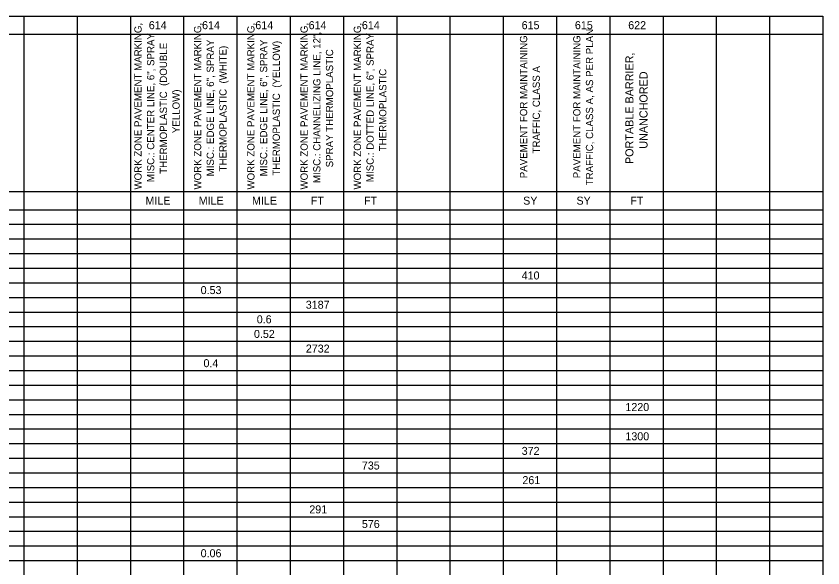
# Model space of a CAD drawing. Extents: x 91011267 to 91022583, y 37007614 to 37014266.
# Drawn here: x 91012044 to 91012802, y 37010707 to 37011225 of the extents above; entities that cross this region are included whole.
import ezdxf

# ---------------------------------------------------------------- set-up
doc = ezdxf.new("R2010")
doc.units = 0
doc.layers.add('SC_Scratch2', color=7, linetype='Continuous')
doc.layers.add('SH_Data', color=7, linetype='Continuous')

msp = doc.modelspace()

# ---------------------------------------------------------------- linework, layer by layer
at = {"layer": 'SC_Scratch2'}
msp.add_lwpolyline([(91011277.35, 37011225.45), (91012802.35, 37011225.45), (91012802.35, 37010175.45), (91011277.35, 37010175.45)], close=True, dxfattribs=at)
at = {"layer": 'SH_Data'}
for p, q in [((91012000.97, 37011225.45), (91012551.92, 37011225.45)), ((91012051.05, 37011225.45), (91012051.05, 37011134.52)), ((91012101.14, 37011225.45), (91012101.14, 37011134.52)), ((91012151.23, 37011225.45), (91012151.23, 37011134.52)), ((91012201.31, 37011225.45), (91012201.31, 37011134.52)), ((91012251.4, 37011225.45), (91012251.4, 37011134.52)), ((91012301.49, 37011225.45), (91012301.49, 37011134.52)), ((91012351.57, 37011225.45), (91012351.57, 37011134.52)), ((91012401.66, 37011225.45), (91012401.66, 37011134.52)), ((91012451.75, 37011225.45), (91012451.75, 37011134.52)), ((91012501.83, 37011225.45), (91012501.83, 37011134.52)), ((91012551.92, 37011225.45), (91012602, 37011225.45)), ((91012551.92, 37011225.45), (91012551.92, 37011134.52)), ((91012602, 37011225.45), (91012652.09, 37011225.45)), ((91012602, 37011225.45), (91012602, 37011134.52)), ((91012652.09, 37011225.45), (91012702.18, 37011225.45)), ((91012652.09, 37011225.45), (91012652.09, 37011134.52)), ((91012702.18, 37011225.45), (91012802.35, 37011225.45)), ((91012702.18, 37011225.45), (91012702.18, 37011134.52)), ((91012752.26, 37011225.45), (91012752.26, 37011134.52)), ((91012802.35, 37011225.45), (91012802.35, 37011134.52)), ((91012000.97, 37011208.44), (91012551.92, 37011208.44)), ((91012551.92, 37011208.44), (91012602, 37011208.44)), ((91012602, 37011208.44), (91012652.09, 37011208.44)), ((91012652.09, 37011208.44), (91012702.18, 37011208.44)), ((91012702.18, 37011208.44), (91012802.35, 37011208.44)), ((91012051.05, 37011134.52), (91012051.05, 37011060.59)), ((91012101.14, 37011134.52), (91012101.14, 37011060.59)), ((91012151.23, 37011134.52), (91012151.23, 37011060.59)), ((91012201.31, 37011134.52), (91012201.31, 37011060.59)), ((91012251.4, 37011134.52), (91012251.4, 37011060.59)), ((91012301.49, 37011134.52), (91012301.49, 37011060.59)), ((91012351.57, 37011134.52), (91012351.57, 37011060.59)), ((91012401.66, 37011134.52), (91012401.66, 37011060.59)), ((91012451.75, 37011134.52), (91012451.75, 37011060.59)), ((91012501.83, 37011134.52), (91012501.83, 37011060.59)), ((91012551.92, 37011134.52), (91012551.92, 37011060.59)), ((91012602, 37011134.52), (91012602, 37011060.59)), ((91012652.09, 37011134.52), (91012652.09, 37011060.59)), ((91012702.18, 37011134.52), (91012702.18, 37011060.59)), ((91012752.26, 37011134.52), (91012752.26, 37011060.59)), ((91012802.35, 37011134.52), (91012802.35, 37011060.59)), ((91012000.97, 37011060.59), (91012551.92, 37011060.59)), ((91012051.05, 37011060.59), (91012051.05, 37011043.58)), ((91012101.14, 37011060.59), (91012101.14, 37011043.58)), ((91012151.23, 37011060.59), (91012151.23, 37011043.58)), ((91012201.31, 37011060.59), (91012201.31, 37011043.58)), ((91012251.4, 37011060.59), (91012251.4, 37011043.58)), ((91012301.49, 37011060.59), (91012301.49, 37011043.58)), ((91012351.57, 37011060.59), (91012351.57, 37011043.58)), ((91012401.66, 37011060.59), (91012401.66, 37011043.58)), ((91012451.75, 37011060.59), (91012451.75, 37011043.58)), ((91012501.83, 37011060.59), (91012501.83, 37011043.58)), ((91012551.92, 37011060.59), (91012602, 37011060.59)), ((91012551.92, 37011060.59), (91012551.92, 37011043.58)), ((91012602, 37011060.59), (91012652.09, 37011060.59)), ((91012602, 37011060.59), (91012602, 37011043.58)), ((91012652.09, 37011060.59), (91012702.18, 37011060.59)), ((91012652.09, 37011060.59), (91012652.09, 37011043.58)), ((91012702.18, 37011060.59), (91012802.35, 37011060.59)), ((91012702.18, 37011060.59), (91012702.18, 37011043.58)), ((91012752.26, 37011060.59), (91012752.26, 37011043.58)), ((91012802.35, 37011060.59), (91012802.35, 37011043.58)), ((91012000.97, 37011043.58), (91012551.92, 37011043.58)), ((91012051.05, 37011043.58), (91012051.05, 37010933.68)), ((91012101.14, 37011043.58), (91012101.14, 37010933.68)), ((91012151.23, 37011043.58), (91012151.23, 37010933.68)), ((91012201.31, 37011043.58), (91012201.31, 37010933.68)), ((91012251.4, 37011043.58), (91012251.4, 37010933.68)), ((91012301.49, 37011043.58), (91012301.49, 37010933.68)), ((91012351.57, 37011043.58), (91012351.57, 37010933.68)), ((91012401.66, 37011043.58), (91012401.66, 37010933.68)), ((91012451.75, 37011043.58), (91012451.75, 37010933.68)), ((91012501.83, 37011043.58), (91012501.83, 37010933.68)), ((91012551.92, 37011043.58), (91012602, 37011043.58)), ((91012551.92, 37011043.58), (91012551.92, 37010933.68)), ((91012602, 37011043.58), (91012652.09, 37011043.58)), ((91012602, 37011043.58), (91012602, 37010933.68)), ((91012652.09, 37011043.58), (91012702.18, 37011043.58)), ((91012652.09, 37011043.58), (91012652.09, 37010933.68)), ((91012702.18, 37011043.58), (91012802.35, 37011043.58)), ((91012702.18, 37011043.58), (91012702.18, 37010933.68)), ((91012752.26, 37011043.58), (91012752.26, 37010933.68)), ((91012802.35, 37011043.58), (91012802.35, 37010933.68)), ((91012000.97, 37011029.85), (91012551.92, 37011029.85)), ((91012551.92, 37011029.85), (91012602, 37011029.85)), ((91012602, 37011029.85), (91012652.09, 37011029.85)), ((91012652.09, 37011029.85), (91012702.18, 37011029.85)), ((91012702.18, 37011029.85), (91012802.35, 37011029.85)), ((91012000.97, 37011016.11), (91012551.92, 37011016.11)), ((91012551.92, 37011016.11), (91012602, 37011016.11)), ((91012602, 37011016.11), (91012652.09, 37011016.11)), ((91012652.09, 37011016.11), (91012702.18, 37011016.11)), ((91012702.18, 37011016.11), (91012802.35, 37011016.11)), ((91012000.97, 37011002.37), (91012551.92, 37011002.37)), ((91012551.92, 37011002.37), (91012602, 37011002.37)), ((91012602, 37011002.37), (91012652.09, 37011002.37)), ((91012652.09, 37011002.37), (91012702.18, 37011002.37)), ((91012702.18, 37011002.37), (91012802.35, 37011002.37)), ((91012000.97, 37010988.63), (91012551.92, 37010988.63)), ((91012551.92, 37010988.63), (91012602, 37010988.63)), ((91012602, 37010988.63), (91012652.09, 37010988.63)), ((91012652.09, 37010988.63), (91012702.18, 37010988.63)), ((91012702.18, 37010988.63), (91012802.35, 37010988.63)), ((91012000.97, 37010974.89), (91012551.92, 37010974.89)), ((91012551.92, 37010974.89), (91012602, 37010974.89)), ((91012602, 37010974.89), (91012652.09, 37010974.89)), ((91012652.09, 37010974.89), (91012702.18, 37010974.89)), ((91012702.18, 37010974.89), (91012802.35, 37010974.89)), ((91012000.97, 37010961.15), (91012551.92, 37010961.15)), ((91012551.92, 37010961.15), (91012602, 37010961.15)), ((91012602, 37010961.15), (91012652.09, 37010961.15)), ((91012652.09, 37010961.15), (91012702.18, 37010961.15)), ((91012702.18, 37010961.15), (91012802.35, 37010961.15)), ((91012000.97, 37010947.42), (91012551.92, 37010947.42)), ((91012551.92, 37010947.42), (91012602, 37010947.42)), ((91012602, 37010947.42), (91012652.09, 37010947.42)), ((91012652.09, 37010947.42), (91012702.18, 37010947.42)), ((91012702.18, 37010947.42), (91012802.35, 37010947.42)), ((91012000.97, 37010933.68), (91012551.92, 37010933.68)), ((91012051.05, 37010933.68), (91012051.05, 37010919.94)), ((91012101.14, 37010933.68), (91012101.14, 37010919.94)), ((91012151.23, 37010933.68), (91012151.23, 37010919.94)), ((91012201.31, 37010933.68), (91012201.31, 37010919.94)), ((91012251.4, 37010933.68), (91012251.4, 37010919.94)), ((91012301.49, 37010933.68), (91012301.49, 37010919.94)), ((91012351.57, 37010933.68), (91012351.57, 37010919.94)), ((91012401.66, 37010933.68), (91012401.66, 37010919.94)), ((91012451.75, 37010933.68), (91012451.75, 37010919.94)), ((91012501.83, 37010933.68), (91012501.83, 37010919.94)), ((91012551.92, 37010933.68), (91012602, 37010933.68)), ((91012551.92, 37010933.68), (91012551.92, 37010919.94)), ((91012602, 37010933.68), (91012652.09, 37010933.68)), ((91012602, 37010933.68), (91012602, 37010919.94)), ((91012652.09, 37010933.68), (91012702.18, 37010933.68)), ((91012652.09, 37010933.68), (91012652.09, 37010919.94)), ((91012702.18, 37010933.68), (91012802.35, 37010933.68)), ((91012702.18, 37010933.68), (91012702.18, 37010919.94)), ((91012752.26, 37010933.68), (91012752.26, 37010919.94)), ((91012802.35, 37010933.68), (91012802.35, 37010919.94)), ((91012000.97, 37010919.94), (91012551.92, 37010919.94)), ((91012051.05, 37010919.94), (91012051.05, 37010892.46)), ((91012101.14, 37010919.94), (91012101.14, 37010892.46)), ((91012151.23, 37010919.94), (91012151.23, 37010892.46)), ((91012201.31, 37010919.94), (91012201.31, 37010892.46)), ((91012251.4, 37010919.94), (91012251.4, 37010892.46)), ((91012301.49, 37010919.94), (91012301.49, 37010892.46)), ((91012351.57, 37010919.94), (91012351.57, 37010892.46)), ((91012401.66, 37010919.94), (91012401.66, 37010892.46)), ((91012451.75, 37010919.94), (91012451.75, 37010892.46)), ((91012501.83, 37010919.94), (91012501.83, 37010892.46)), ((91012551.92, 37010919.94), (91012602, 37010919.94)), ((91012551.92, 37010919.94), (91012551.92, 37010892.46)), ((91012602, 37010919.94), (91012652.09, 37010919.94)), ((91012602, 37010919.94), (91012602, 37010892.46)), ((91012652.09, 37010919.94), (91012702.18, 37010919.94)), ((91012652.09, 37010919.94), (91012652.09, 37010892.46)), ((91012702.18, 37010919.94), (91012802.35, 37010919.94)), ((91012702.18, 37010919.94), (91012702.18, 37010892.46)), ((91012752.26, 37010919.94), (91012752.26, 37010892.46)), ((91012802.35, 37010919.94), (91012802.35, 37010892.46)), ((91012000.97, 37010906.2), (91012551.92, 37010906.2)), ((91012551.92, 37010906.2), (91012602, 37010906.2)), ((91012602, 37010906.2), (91012652.09, 37010906.2)), ((91012652.09, 37010906.2), (91012702.18, 37010906.2)), ((91012702.18, 37010906.2), (91012802.35, 37010906.2)), ((91012000.97, 37010892.46), (91012551.92, 37010892.46)), ((91012051.05, 37010892.46), (91012051.05, 37010878.72)), ((91012101.14, 37010892.46), (91012101.14, 37010878.72)), ((91012151.23, 37010892.46), (91012151.23, 37010878.72)), ((91012201.31, 37010892.46), (91012201.31, 37010878.72)), ((91012251.4, 37010892.46), (91012251.4, 37010878.72)), ((91012301.49, 37010892.46), (91012301.49, 37010878.72)), ((91012351.57, 37010892.46), (91012351.57, 37010878.72)), ((91012401.66, 37010892.46), (91012401.66, 37010878.72)), ((91012451.75, 37010892.46), (91012451.75, 37010878.72)), ((91012501.83, 37010892.46), (91012501.83, 37010878.72)), ((91012551.92, 37010892.46), (91012602, 37010892.46)), ((91012551.92, 37010892.46), (91012551.92, 37010878.72)), ((91012602, 37010892.46), (91012652.09, 37010892.46)), ((91012602, 37010892.46), (91012602, 37010878.72)), ((91012652.09, 37010892.46), (91012702.18, 37010892.46)), ((91012652.09, 37010892.46), (91012652.09, 37010878.72)), ((91012702.18, 37010892.46), (91012802.35, 37010892.46)), ((91012702.18, 37010892.46), (91012702.18, 37010878.72)), ((91012752.26, 37010892.46), (91012752.26, 37010878.72)), ((91012802.35, 37010892.46), (91012802.35, 37010878.72)), ((91012000.97, 37010878.72), (91012551.92, 37010878.72)), ((91012051.05, 37010878.72), (91012051.05, 37010864.99)), ((91012101.14, 37010878.72), (91012101.14, 37010864.99)), ((91012151.23, 37010878.72), (91012151.23, 37010864.99)), ((91012201.31, 37010878.72), (91012201.31, 37010864.99)), ((91012251.4, 37010878.72), (91012251.4, 37010864.99)), ((91012301.49, 37010878.72), (91012301.49, 37010864.99)), ((91012351.57, 37010878.72), (91012351.57, 37010864.99)), ((91012401.66, 37010878.72), (91012401.66, 37010864.99)), ((91012451.75, 37010878.72), (91012451.75, 37010864.99)), ((91012501.83, 37010878.72), (91012501.83, 37010864.99)), ((91012551.92, 37010878.72), (91012602, 37010878.72)), ((91012551.92, 37010878.72), (91012551.92, 37010864.99)), ((91012602, 37010878.72), (91012652.09, 37010878.72)), ((91012602, 37010878.72), (91012602, 37010864.99)), ((91012652.09, 37010878.72), (91012702.18, 37010878.72)), ((91012652.09, 37010878.72), (91012652.09, 37010864.99)), ((91012702.18, 37010878.72), (91012802.35, 37010878.72)), ((91012702.18, 37010878.72), (91012702.18, 37010864.99)), ((91012752.26, 37010878.72), (91012752.26, 37010864.99)), ((91012802.35, 37010878.72), (91012802.35, 37010864.99)), ((91012000.97, 37010864.99), (91012551.92, 37010864.99)), ((91012051.05, 37010864.99), (91012051.05, 37010851.25)), ((91012101.14, 37010864.99), (91012101.14, 37010851.25)), ((91012151.23, 37010864.99), (91012151.23, 37010851.25)), ((91012201.31, 37010864.99), (91012201.31, 37010851.25)), ((91012251.4, 37010864.99), (91012251.4, 37010851.25)), ((91012301.49, 37010864.99), (91012301.49, 37010851.25)), ((91012351.57, 37010864.99), (91012351.57, 37010851.25)), ((91012401.66, 37010864.99), (91012401.66, 37010851.25)), ((91012451.75, 37010864.99), (91012451.75, 37010851.25)), ((91012501.83, 37010864.99), (91012501.83, 37010851.25)), ((91012551.92, 37010864.99), (91012602, 37010864.99)), ((91012551.92, 37010864.99), (91012551.92, 37010851.25)), ((91012602, 37010864.99), (91012652.09, 37010864.99)), ((91012602, 37010864.99), (91012602, 37010851.25)), ((91012652.09, 37010864.99), (91012702.18, 37010864.99)), ((91012652.09, 37010864.99), (91012652.09, 37010851.25)), ((91012702.18, 37010864.99), (91012802.35, 37010864.99)), ((91012702.18, 37010864.99), (91012702.18, 37010851.25)), ((91012752.26, 37010864.99), (91012752.26, 37010851.25)), ((91012802.35, 37010864.99), (91012802.35, 37010851.25)), ((91012000.97, 37010851.25), (91012551.92, 37010851.25)), ((91012051.05, 37010851.25), (91012051.05, 37010645.17)), ((91012101.14, 37010851.25), (91012101.14, 37010645.17)), ((91012151.23, 37010851.25), (91012151.23, 37010645.17)), ((91012201.31, 37010851.25), (91012201.31, 37010645.17)), ((91012251.4, 37010851.25), (91012251.4, 37010645.17)), ((91012301.49, 37010851.25), (91012301.49, 37010645.17)), ((91012351.57, 37010851.25), (91012351.57, 37010645.17)), ((91012401.66, 37010851.25), (91012401.66, 37010645.17)), ((91012451.75, 37010851.25), (91012451.75, 37010645.17)), ((91012501.83, 37010851.25), (91012501.83, 37010645.17)), ((91012551.92, 37010851.25), (91012602, 37010851.25)), ((91012551.92, 37010851.25), (91012551.92, 37010645.17)), ((91012602, 37010851.25), (91012652.09, 37010851.25)), ((91012602, 37010851.25), (91012602, 37010645.17)), ((91012652.09, 37010851.25), (91012702.18, 37010851.25)), ((91012652.09, 37010851.25), (91012652.09, 37010645.17)), ((91012702.18, 37010851.25), (91012802.35, 37010851.25)), ((91012702.18, 37010851.25), (91012702.18, 37010645.17)), ((91012752.26, 37010851.25), (91012752.26, 37010645.17)), ((91012802.35, 37010851.25), (91012802.35, 37010645.17)), ((91012000.97, 37010837.51), (91012551.92, 37010837.51)), ((91012551.92, 37010837.51), (91012602, 37010837.51)), ((91012602, 37010837.51), (91012652.09, 37010837.51)), ((91012652.09, 37010837.51), (91012702.18, 37010837.51)), ((91012702.18, 37010837.51), (91012802.35, 37010837.51)), ((91012000.97, 37010823.77), (91012551.92, 37010823.77)), ((91012551.92, 37010823.77), (91012602, 37010823.77)), ((91012602, 37010823.77), (91012652.09, 37010823.77)), ((91012652.09, 37010823.77), (91012702.18, 37010823.77)), ((91012702.18, 37010823.77), (91012802.35, 37010823.77)), ((91012000.97, 37010810.03), (91012551.92, 37010810.03)), ((91012551.92, 37010810.03), (91012602, 37010810.03)), ((91012602, 37010810.03), (91012652.09, 37010810.03)), ((91012652.09, 37010810.03), (91012702.18, 37010810.03)), ((91012702.18, 37010810.03), (91012802.35, 37010810.03)), ((91012000.97, 37010796.29), (91012551.92, 37010796.29)), ((91012551.92, 37010796.29), (91012602, 37010796.29)), ((91012602, 37010796.29), (91012652.09, 37010796.29)), ((91012652.09, 37010796.29), (91012702.18, 37010796.29)), ((91012702.18, 37010796.29), (91012802.35, 37010796.29)), ((91012000.97, 37010782.56), (91012551.92, 37010782.56)), ((91012551.92, 37010782.56), (91012602, 37010782.56)), ((91012602, 37010782.56), (91012652.09, 37010782.56)), ((91012652.09, 37010782.56), (91012702.18, 37010782.56)), ((91012702.18, 37010782.56), (91012802.35, 37010782.56)), ((91012000.97, 37010768.82), (91012551.92, 37010768.82)), ((91012551.92, 37010768.82), (91012602, 37010768.82)), ((91012602, 37010768.82), (91012652.09, 37010768.82)), ((91012652.09, 37010768.82), (91012702.18, 37010768.82)), ((91012702.18, 37010768.82), (91012802.35, 37010768.82)), ((91012000.97, 37010755.08), (91012551.92, 37010755.08)), ((91012551.92, 37010755.08), (91012602, 37010755.08)), ((91012602, 37010755.08), (91012652.09, 37010755.08)), ((91012652.09, 37010755.08), (91012702.18, 37010755.08)), ((91012702.18, 37010755.08), (91012802.35, 37010755.08)), ((91012000.97, 37010741.34), (91012551.92, 37010741.34)), ((91012551.92, 37010741.34), (91012602, 37010741.34)), ((91012602, 37010741.34), (91012652.09, 37010741.34)), ((91012652.09, 37010741.34), (91012702.18, 37010741.34)), ((91012702.18, 37010741.34), (91012802.35, 37010741.34)), ((91012000.97, 37010727.6), (91012551.92, 37010727.6)), ((91012551.92, 37010727.6), (91012602, 37010727.6)), ((91012602, 37010727.6), (91012652.09, 37010727.6)), ((91012652.09, 37010727.6), (91012702.18, 37010727.6)), ((91012702.18, 37010727.6), (91012802.35, 37010727.6)), ((91012000.97, 37010713.86), (91012551.92, 37010713.86)), ((91012551.92, 37010713.86), (91012602, 37010713.86)), ((91012602, 37010713.86), (91012652.09, 37010713.86)), ((91012652.09, 37010713.86), (91012702.18, 37010713.86)), ((91012702.18, 37010713.86), (91012802.35, 37010713.86))]:
    msp.add_line(p, q, dxfattribs=at)

# ---------------------------------------------------------------- texts
for s, p in [('614', (91012168.55, 37011213.19)), ('614', (91012218.64, 37011213.19)), ('614', (91012268.73, 37011213.19)), ('614', (91012318.81, 37011213.19)), ('614', (91012368.9, 37011213.19)), ('615', (91012519.12, 37011213.19)), ('615', (91012569.2, 37011213.19)), ('622', (91012619.35, 37011213.19)), ('MILE', (91012165.4, 37011048.33)), ('MILE', (91012215.49, 37011048.33)), ('MILE', (91012265.58, 37011048.33)), ('FT', (91012320.8, 37011048.33)), ('FT', (91012370.89, 37011048.33)), ('SY', (91012520.55, 37011048.33)), ('SY', (91012570.64, 37011048.33)), ('FT', (91012621.32, 37011048.33)), ('410', (91012519.16, 37010978)), ('0.53', (91012217.3, 37010964.26)), ('3187', (91012316.15, 37010950.52)), ('0.6', (91012270.04, 37010936.79)), ('0.52', (91012267.43, 37010923.05)), ('2732', (91012316.19, 37010909.31)), ('0.4', (91012219.97, 37010895.57)), ('1220', (91012616.68, 37010854.36)), ('1300', (91012616.68, 37010826.88)), ('372', (91012519.18, 37010813.14)), ('735', (91012368.86, 37010799.4)), ('261', (91012519.8, 37010785.66)), ('291', (91012319.46, 37010758.19)), ('576', (91012368.88, 37010744.45)), ('0.06', (91012217.3, 37010716.97))]:
    msp.add_text(s, height=7.523, dxfattribs=at).set_placement(p)
for s, height, p in [('WORK ZONE PAVEMENT MARKING, ', 6.821, (91012161.78, 37011062.51)), ('WORK ZONE PAVEMENT MARKING, ', 6.821, (91012217.83, 37011062.51)), ('WORK ZONE PAVEMENT MARKING, ', 6.821, (91012267.92, 37011062.51)), ('WORK ZONE PAVEMENT MARKING, ', 6.821, (91012318, 37011062.51)), ('WORK ZONE PAVEMENT MARKING, ', 6.821, (91012368.09, 37011062.51)), ('MISC.: CENTER LINE, 6", SPRAY ', 6.821, (91012173.71, 37011069.48)), ('MISC.: CHANNELIZING LINE, 12", ', 6.821, (91012329.94, 37011068.57)), ('MISC.: DOTTED LINE, 6", SPRAY ', 6.821, (91012380.03, 37011069.49)), ('PAVEMENT FOR MAINTAINING ', 6.821, (91012524.32, 37011073.12)), ('PAVEMENT FOR MAINTAINING ', 6.821, (91012574.4, 37011073.12)), ('TRAFFIC, CLASS A, AS PER PLAN', 6.821, (91012586.34, 37011066.49)), ('THERMOPLASTIC  (DOUBLE ', 6.821, (91012185.65, 37011077.26)), ('MISC.: EDGE LINE, 6", SPRAY ', 6.821, (91012229.77, 37011074.92)), ('MISC.: EDGE LINE, 6", SPRAY ', 6.821, (91012279.85, 37011074.92)), ('THERMOPLASTIC  (YELLOW)', 6.821, (91012291.79, 37011075.54)), ('THERMOPLASTIC  (WHITE)', 6.821, (91012241.7, 37011079.56)), ('SPRAY THERMOPLASTIC', 6.821, (91012341.88, 37011083.35)), ('PORTABLE BARRIER, ', 7.5789, (91012624.21, 37011086.48)), ('THERMOPLASTIC', 6.821, (91012391.96, 37011098.49)), ('TRAFFIC, CLASS A', 6.821, (91012536.25, 37011096.42)), ('UNANCHORED', 7.579, (91012637.47, 37011100.86)), ('YELLOW)', 6.821, (91012197.59, 37011115.51))]:
    msp.add_text(s, height=height, rotation=90, dxfattribs=at).set_placement(p)

doc.saveas('drawing.dxf')
